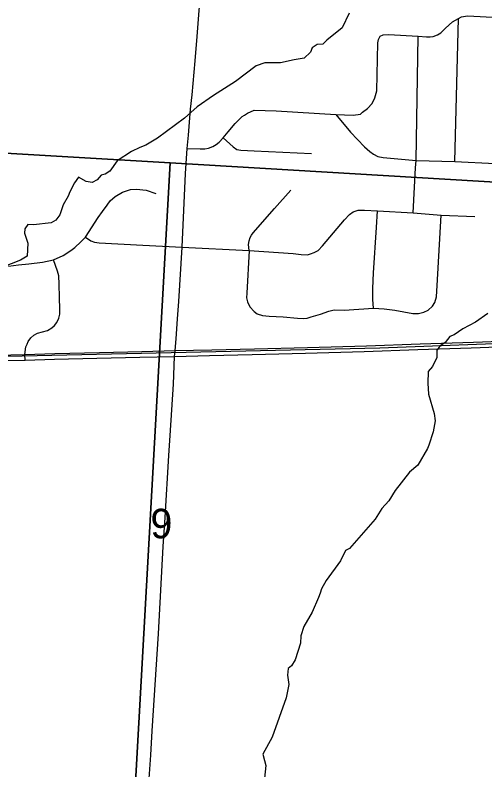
# Model space of a CAD drawing. Extents: x 0 to 34, y 0 to 22.
# Drawn here: x 7.53 to 8.197, y 16.702 to 17.774 of the extents above; entities that cross this region are included whole.
import ezdxf

# ---------------------------------------------------------------- set-up
doc = ezdxf.new("R2010")
doc.units = 0
for name, color, linetype in [('GM_X_County_Road', 7, 'Continuous'), ('GM_X_Minor_River', 7, 'Continuous'), ('GM_X_Rail_Line', 7, 'Continuous'), ('GM_X_Section', 7, 'Continuous'), ('GM_X_Section_Text', 7, 'Continuous'), ('GM_X_Township_Road', 7, 'Continuous'), ('GM_X_US_Route', 7, 'Continuous')]:
    doc.layers.add(name, color=color, linetype=linetype)

msp = doc.modelspace()

# ---------------------------------------------------------------- linework, layer by layer
at = {"layer": 'GM_X_County_Road'}
for points in [[(7.7561, 17.2894), (7.7569, 17.2976), (7.7584, 17.3144), (7.7604, 17.3425), (7.7621, 17.3671), (7.7668, 17.4443), (7.7715, 17.549), (7.7739, 17.5845), (7.7759, 17.6032), (7.779, 17.6404), (7.7811, 17.6605), (7.7856, 17.7091), (7.7883, 17.7434), (7.7911, 17.7802), (7.7933, 17.8057), (7.7967, 17.8433), (7.8023, 17.9171), (7.8052, 17.9615), (7.8055, 17.9654)], [(7.7222, 16.7232), (7.7245, 16.7578), (7.7332, 16.8953), (7.7398, 17.0194), (7.7427, 17.0604), (7.7482, 17.1487), (7.7501, 17.177), (7.7544, 17.25), (7.7561, 17.2894)], [(7.7068, 16.4655), (7.7106, 16.5304), (7.7116, 16.5509), (7.7183, 16.6638), (7.7222, 16.7232)]]:
    msp.add_lwpolyline(points, dxfattribs=at)
at = {"layer": 'GM_X_Minor_River'}
for points in [[(8.004, 17.7767), (7.9941, 17.7555), (7.9725, 17.7384), (7.9668, 17.7324), (7.9585, 17.732), (7.9517, 17.7275), (7.949, 17.721), (7.9403, 17.7127), (7.9346, 17.7116), (7.9259, 17.7101), (7.9065, 17.7059), (7.8842, 17.706), (7.8721, 17.7018), (7.8425, 17.6795), (7.8114, 17.6598), (7.7883, 17.6436), (7.7701, 17.6277), (7.7321, 17.5993), (7.7155, 17.5894), (7.7067, 17.586), (7.695, 17.5804), (7.6745, 17.5671), (7.6643, 17.5524), (7.6574, 17.5478), (7.6521, 17.5467), (7.6464, 17.5399), (7.6389, 17.5361), (7.6305, 17.5376), (7.6199, 17.5437), (7.6139, 17.5358), (7.6074, 17.5229), (7.6051, 17.5168), (7.5979, 17.5047), (7.5933, 17.4903), (7.5876, 17.4827), (7.5808, 17.4789), (7.5558, 17.4759), (7.5475, 17.4767), (7.5437, 17.4706), (7.5429, 17.4642), (7.5478, 17.4501), (7.547, 17.4315), (7.5375, 17.4259), (7.511, 17.4153)], [(8.2012, 17.3504), (8.1834, 17.3379), (8.1656, 17.3284), (8.1534, 17.3201), (8.147, 17.3178), (8.1405, 17.3091), (8.1329, 17.3038), (8.1288, 17.2981), (8.1287, 17.2879), (8.1223, 17.275), (8.1166, 17.2678), (8.1158, 17.2511), (8.1169, 17.2355), (8.1248, 17.2082), (8.1263, 17.1979), (8.1236, 17.1824), (8.1171, 17.1634), (8.1156, 17.1585), (8.1015, 17.135), (8.0898, 17.1248), (8.0693, 17.099), (8.0605, 17.0842), (8.0507, 17.0732), (8.0412, 17.0584), (8.0047, 17.0168), (7.9991, 17.0137), (7.9918, 16.9993), (7.9713, 16.9713), (7.9649, 16.9595), (7.963, 16.9531), (7.9607, 16.947), (7.9515, 16.9261), (7.9398, 16.9061), (7.9356, 16.8928), (7.9348, 16.8821), (7.9275, 16.8586), (7.9222, 16.8499), (7.9173, 16.8461), (7.9165, 16.8366), (7.9184, 16.8237), (7.9149, 16.8044), (7.8948, 16.7486), (7.8815, 16.7247), (7.8841, 16.7156), (7.8856, 16.7084), (7.8825, 16.6769)]]:
    msp.add_lwpolyline(points, dxfattribs=at)
at = {"layer": 'GM_X_Rail_Line'}
msp.add_lwpolyline([(2.1, 17.1885), (2.293, 17.1932), (3.2433, 17.211), (3.5049, 17.2168), (5.1641, 17.2441), (5.3961, 17.2441), (6.3843, 17.2591), (6.7484, 17.272), (7.243, 17.2836), (8.0477, 17.3015), (8.4974, 17.3184), (8.9, 17.3324)], dxfattribs=at)
at = {"layer": 'GM_X_Section'}
for points in [[(7.2905, 18.1831), (7.7604, 18.1481), (8.3042, 18.1163), (8.2754, 17.5329), (7.7498, 17.5639), (7.2571, 17.593)], [(7.2571, 17.593), (7.7498, 17.5639), (7.694, 16.5662), (7.1941, 16.5986)], [(7.7498, 17.5639), (8.2754, 17.5329), (8.2225, 16.5336), (7.694, 16.5662)]]:
    msp.add_lwpolyline(points, close=True, dxfattribs=at)
at = {"layer": 'GM_X_Township_Road'}
for p, q in [((8.1543, 17.5659), (8.1593, 17.7688)), ((8.0949, 17.4929), (8.0985, 17.557))]:
    msp.add_line(p, q, dxfattribs=at)
for points in [[(7.7739, 17.5845), (7.7924, 17.5839), (7.7993, 17.5841), (7.8043, 17.5851), (7.8103, 17.5872), (7.8154, 17.59), (7.8193, 17.5933), (7.8252, 17.5997), (7.8325, 17.6081), (7.8422, 17.62), (7.8478, 17.6257), (7.8523, 17.6297), (7.8555, 17.6319), (7.8599, 17.6348), (7.8693, 17.639), (7.9004, 17.6378), (7.9852, 17.6326), (8.0099, 17.6317), (8.0201, 17.6334), (8.0231, 17.6361), (8.03, 17.6412), (8.0367, 17.6483), (8.0407, 17.6565), (8.0433, 17.6665), (8.0447, 17.7344), (8.0458, 17.7394), (8.0483, 17.7438), (8.0526, 17.746), (8.0601, 17.7461), (8.1023, 17.7437), (8.114, 17.7428), (8.1193, 17.7431), (8.1235, 17.7434), (8.1294, 17.7456), (8.1344, 17.7488), (8.1411, 17.7553), (8.151, 17.7644), (8.1593, 17.7688), (8.1639, 17.7712), (8.1721, 17.773), (8.2166, 17.7704)], [(8.0985, 17.557), (8.0991, 17.5676), (8.1023, 17.7437)], [(7.9852, 17.6326), (8.0061, 17.6076), (8.026, 17.5866), (8.0336, 17.5802), (8.0388, 17.5766), (8.0449, 17.573), (8.0525, 17.5716), (8.063, 17.5705), (8.0991, 17.5676), (8.1543, 17.5659), (8.2114, 17.5632), (8.2516, 17.561)], [(7.8252, 17.5997), (7.8396, 17.587), (7.8447, 17.5831), (7.8505, 17.5819), (7.8692, 17.5812), (7.9505, 17.5772)], [(7.5202, 17.4172), (7.5345, 17.4191), (7.549, 17.4207), (7.5687, 17.4232), (7.584, 17.4264), (7.5979, 17.4327), (7.6089, 17.4396), (7.6147, 17.444), (7.623, 17.4519), (7.6298, 17.4586), (7.6475, 17.4863), (7.6537, 17.4951), (7.6603, 17.5042), (7.6646, 17.5103), (7.6717, 17.5162), (7.6821, 17.5224), (7.6937, 17.5263), (7.7022, 17.5267), (7.7158, 17.5255), (7.7297, 17.5205)], [(7.8622, 17.4397), (7.861, 17.4484), (7.8619, 17.4535), (7.8634, 17.458), (7.8653, 17.4614), (7.8678, 17.4647), (7.8983, 17.4992), (7.9211, 17.5252)], [(7.7668, 17.4443), (7.8622, 17.4397), (7.9245, 17.4354), (7.9362, 17.4342), (7.9449, 17.4337), (7.9493, 17.4348), (7.9543, 17.4366), (7.9601, 17.4398), (7.9662, 17.4465), (7.9975, 17.4833), (8.0045, 17.4906), (8.01, 17.4944), (8.0167, 17.4967), (8.0258, 17.497), (8.0445, 17.4958), (8.0949, 17.4929), (8.1349, 17.49), (8.1825, 17.4879)], [(7.8622, 17.4397), (7.8587, 17.379), (7.8583, 17.3724), (7.8597, 17.3668), (7.8629, 17.3599), (7.8691, 17.3532), (7.8736, 17.3499), (7.8809, 17.3476), (7.8907, 17.3463), (7.9103, 17.3453), (7.9307, 17.3437), (7.9392, 17.343), (7.9443, 17.3435), (7.9502, 17.3453), (7.9636, 17.3494), (7.9754, 17.3535), (7.9829, 17.3553), (7.997, 17.355), (8.0389, 17.3576), (8.0539, 17.357), (8.0689, 17.355), (8.0948, 17.3504), (8.1024, 17.3502), (8.1102, 17.3519), (8.1163, 17.355), (8.1224, 17.3608), (8.1259, 17.3659), (8.1282, 17.374), (8.1292, 17.39), (8.1349, 17.49)], [(8.0389, 17.3576), (8.038, 17.3699), (8.0377, 17.3859), (8.0387, 17.408), (8.043, 17.4724), (8.0445, 17.4958)], [(7.6298, 17.4586), (7.6371, 17.4534), (7.6425, 17.4513), (7.6491, 17.4507), (7.7109, 17.4474), (7.7668, 17.4443)], [(7.5439, 17.2841), (7.5437, 17.2921), (7.5448, 17.3031), (7.5466, 17.3069), (7.5484, 17.3106), (7.552, 17.3157), (7.5563, 17.3193), (7.5613, 17.3221), (7.5684, 17.3241), (7.5757, 17.3262), (7.5819, 17.3297), (7.5858, 17.3332), (7.5888, 17.3374), (7.5919, 17.3438), (7.5931, 17.3494), (7.5932, 17.3562), (7.5925, 17.3728), (7.5923, 17.3918), (7.5917, 17.4038), (7.5898, 17.4101), (7.584, 17.4264)]]:
    msp.add_lwpolyline(points, dxfattribs=at)
at = {"layer": 'GM_X_US_Route'}
for points in [[(6.8191, 17.2765), (6.8875, 17.2779), (6.9485, 17.2792), (7.0087, 17.2802), (7.2063, 17.284), (7.2592, 17.2851), (7.3503, 17.2875), (7.4263, 17.2893), (7.4829, 17.2907), (7.5437, 17.2921), (7.5862, 17.2933), (7.6493, 17.2948), (7.7096, 17.2963), (7.7569, 17.2976), (7.809, 17.2987), (7.8698, 17.3002), (7.9452, 17.302), (8.029, 17.3045), (8.105, 17.3072), (8.1806, 17.3096), (8.2565, 17.3123)], [(6.8194, 17.2685), (6.8878, 17.2699), (6.9488, 17.2712), (7.009, 17.2722), (7.2066, 17.276), (7.2595, 17.2771), (7.3506, 17.2795), (7.4266, 17.2813), (7.4866, 17.283), (7.5439, 17.2841), (7.5855, 17.2852), (7.6458, 17.2867), (7.7068, 17.2883), (7.7561, 17.2894), (7.8059, 17.2906), (7.8666, 17.2921), (7.9419, 17.294), (8.0253, 17.2963), (8.1015, 17.299), (8.1773, 17.3016), (8.2532, 17.3043)]]:
    msp.add_lwpolyline(points, dxfattribs=at)

# ---------------------------------------------------------------- texts
at = {"layer": 'GM_X_Section_Text'}
msp.add_text('9', height=0.0419, rotation=0, dxfattribs=at).set_placement((7.7219, 17.0311))

doc.saveas('drawing.dxf')
